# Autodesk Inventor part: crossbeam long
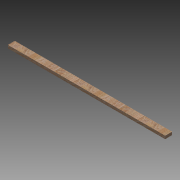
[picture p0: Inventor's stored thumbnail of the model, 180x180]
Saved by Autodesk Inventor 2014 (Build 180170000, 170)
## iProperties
Created: 2014-08
Part Number: crossbeam long
Material: Generic
Document SubType Name: Modeling
Designer: Patrick Rice
Density: 1 g/cm^3
Appearance: Red Oak - Natural
Author: Patrick Rice
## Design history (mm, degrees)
sketch "Sketch1"
  geometry: L1 (1003.3, -44.45)-(-1003.3, -44.45); L2 (-1003.3, -44.45)-(-1003.3, 44.45); L3 (-1003.3, 44.45)-(1003.3, 44.45); L4 (1003.3, 44.45)-(1003.3, -44.45); L5 (1003.3, -44.45)-(-1003.3, 44.45); L6 (-1003.3, -44.45)-(1003.3, 44.45); 1 further point
  constraints: 12 end point, 2 midpoint, 2 parallel, 1 horizontal, 1 perpendicular
  dimensions: "d0" = 88.9 distance of L1.end L2.end; "d1" = 2006.6 distance of L2.end L3.end
extrude "Extrusion1" new body sketch "Sketch1" distance "d2" = 38.1; taper "d3" = 0 deg
body "Solid1"
